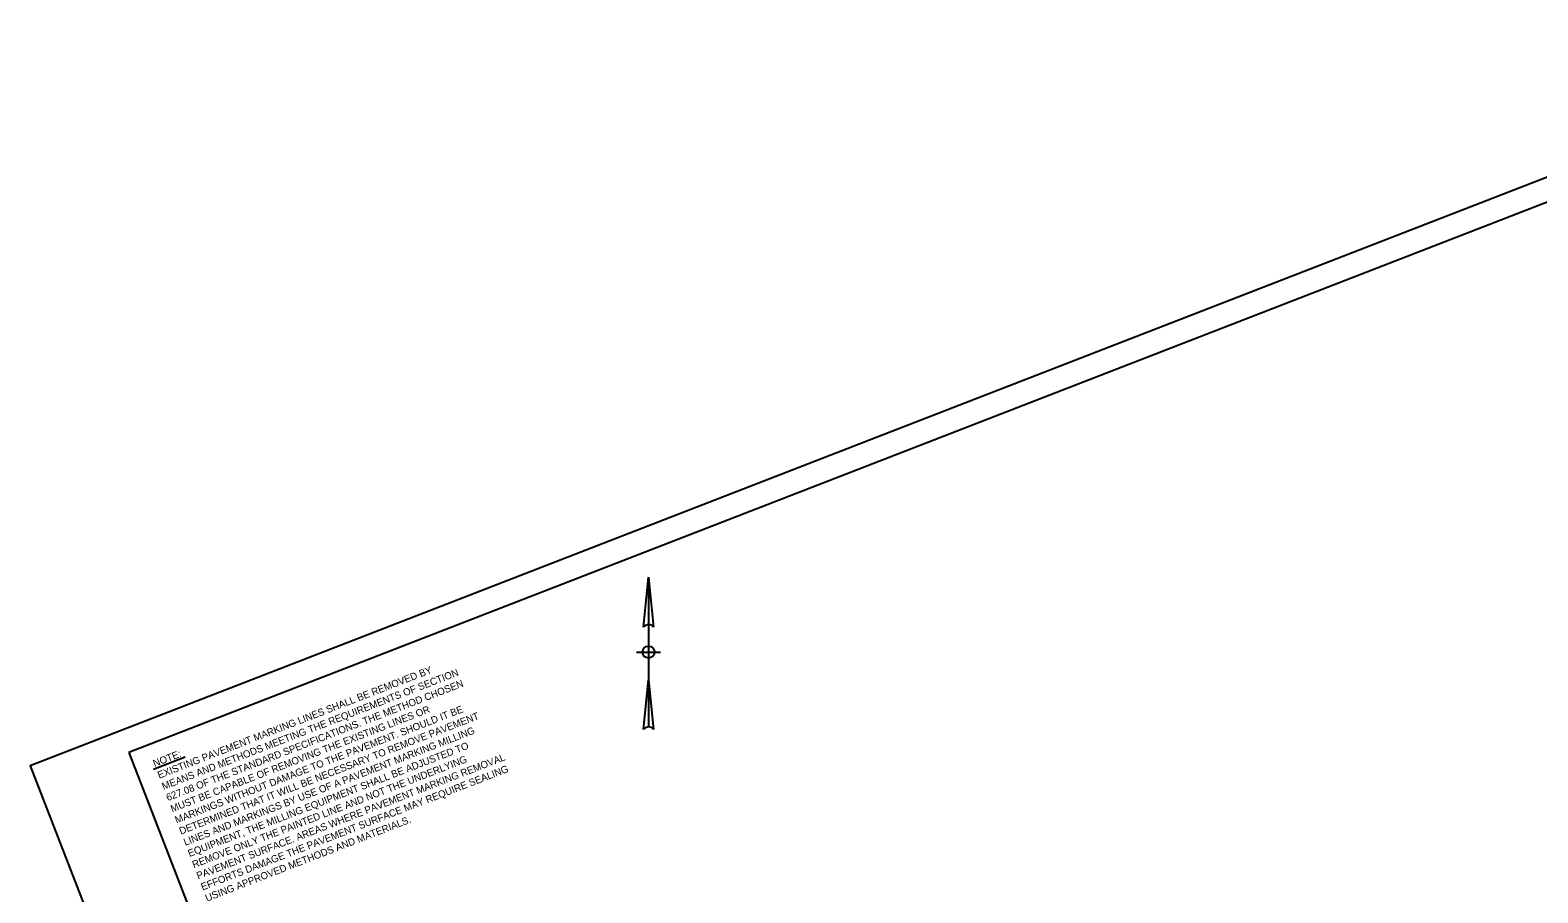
# Model space of a CAD drawing. Extents: x 1669098 to 1670090, y 339554 to 340375.
# Drawn here: x 1669098 to 1669728, y 340014 to 340375 of the extents above; entities that cross this region are included whole.
import ezdxf

# ---------------------------------------------------------------- set-up
doc = ezdxf.new("R2010")
doc.units = 0
for name, color, linetype in [('ANNOTATION', 7, 'Continuous'), ('BORDER', 7, 'Continuous'), ('H_V CONTROLS', 7, 'Continuous'), ('PLOT BOUNDARY', 7, 'Continuous')]:
    doc.layers.add(name, color=color, linetype=linetype)

msp = doc.modelspace()

# ---------------------------------------------------------------- linework, layer by layer
at = {"layer": 'ANNOTATION'}
msp.add_line((1669149.84, 340065.92), (1669162.97, 340071.01), dxfattribs=at)
at = {"layer": 'BORDER'}
for p, q in [((1669885.31, 340362.17), (1669139.46, 340072.86)), ((1669139.46, 340072.86), (1669329.32, 339583.39))]:
    msp.add_line(p, q, dxfattribs=at)
at = {"layer": 'H_V CONTROLS'}
for p, q in [((1669354.62, 340125.23), (1669356.7, 340146.06)), ((1669356.7, 340146.06), (1669356.7, 340083.56)), ((1669356.7, 340146.06), (1669358.78, 340125.23)), ((1669351.7, 340114.81), (1669361.7, 340114.81)), ((1669354.62, 340082.44), (1669356.7, 340103.28)), ((1669356.7, 340103.28), (1669358.78, 340082.44))]:
    msp.add_line(p, q, dxfattribs=at)
msp.add_circle((1669356.7, 340114.81), 2.5, dxfattribs=at)
for centre in [(1669356.7, 340123.85), (1669356.7, 340081.06)]:
    msp.add_arc(centre, 2.5, 33.55731, 146.44269, dxfattribs=at)
at = {"layer": 'PLOT BOUNDARY'}
msp.add_lwpolyline([(1669297.13, 339554.5), (1670089.6, 339861.9), (1669890.69, 340374.67), (1669098.22, 340067.27)], close=True, dxfattribs=at)

# ---------------------------------------------------------------- texts
at = {"layer": 'ANNOTATION'}
for s, p in [('EXISTING PAVEMENT MARKING LINES SHALL BE REMOVED BY ', (1669152.16, 340061.88)), ('MEANS AND METHODS MEETING THE REQUIREMENTS OF SECTION ', (1669153.97, 340057.2)), ('627.08 OF THE STANDARD SPECIFICATIONS. THE METHOD CHOSEN ', (1669155.78, 340052.53)), ('MUST BE CAPABLE OF REMOVING THE EXISTING LINES OR ', (1669157.59, 340047.86)), ('MARKINGS WITHOUT DAMAGE TO THE PAVEMENT. SHOULD IT BE ', (1669159.41, 340043.19)), ('DETERMINED THAT IT WILL BE NECESSARY TO REMOVE PAVEMENT ', (1669161.22, 340038.52)), ('LINES AND MARKINGS BY USE OF A PAVEMENT MARKING MILLING ', (1669163.03, 340033.85)), ('EQUIPMENT, THE MILLING EQUIPMENT SHALL BE ADJUSTED TO ', (1669164.84, 340029.18)), ('NOTE:', (1669150.26, 340066.76)), ('REMOVE ONLY THE PAINTED LINE AND NOT THE UNDERLYING ', (1669166.65, 340024.51)), ('PAVEMENT SURFACE. AREAS WHERE PAVEMENT MARKING REMOVAL ', (1669168.46, 340019.84)), ('EFFORTS DAMAGE THE PAVEMENT SURFACE MAY REQUIRE SEALING ', (1669170.28, 340015.17)), ('USING APPROVED METHODS AND MATERIALS.', (1669172.09, 340010.5))]:
    msp.add_text(s, height=3, rotation=21.20129, dxfattribs=at).set_placement(p)

doc.saveas('drawing.dxf')
